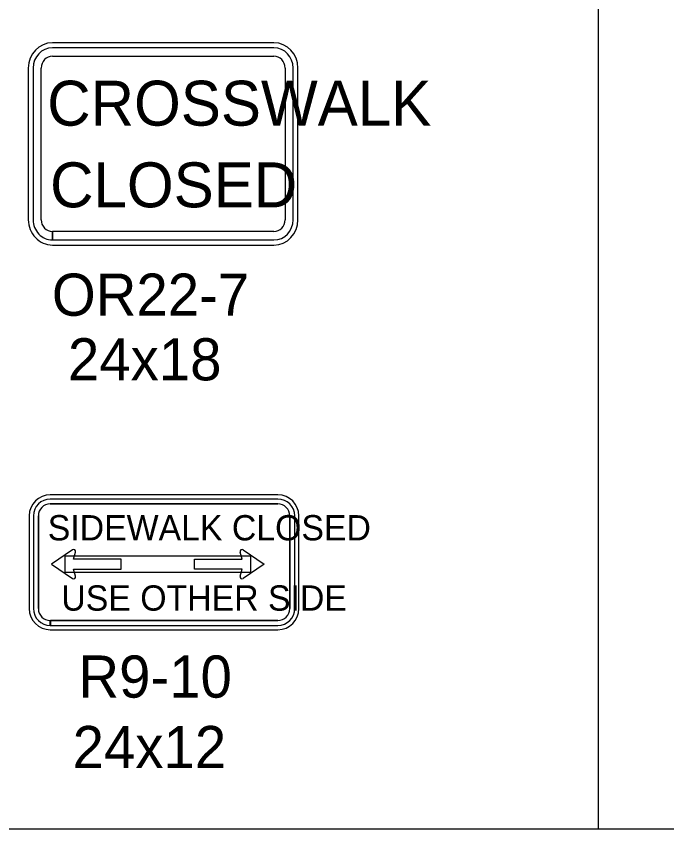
# Model space of a CAD drawing. Extents: x 1458 to 4498, y 17709 to 24109.
# Drawn here: x 2925.6 to 3157.1, y 20667.1 to 20956.1 of the extents above; entities that cross this region are included whole.
import ezdxf

# ---------------------------------------------------------------- set-up
doc = ezdxf.new("R2010")
doc.units = 0
doc.layers.add('P_ODOT_PLAN_TBlock', color=7, linetype='Continuous')
doc.layers.add('P_TRAF_TCP_General', color=7, linetype='Continuous')

msp = doc.modelspace()

# ---------------------------------------------------------------- linework, layer by layer
at = {"layer": 'P_ODOT_PLAN_TBlock'}
for p, q in [((3132.73, 21909.14), (3132.73, 20667.08)), ((1458.44, 20667.08), (3378.44, 20667.08))]:
    msp.add_line(p, q, dxfattribs=at)
at = {"layer": 'P_TRAF_TCP_General'}
for p, q in [((3017.31, 20946.68), (2938.49, 20946.68)), ((3017.31, 20944.88), (2938.49, 20944.88)), ((2938.49, 20941.88), (3017.31, 20941.88)), ((2929.92, 20937.68), (2929.92, 20883.71)), ((2931.63, 20937.68), (2931.63, 20883.71)), ((2934.49, 20883.71), (2934.49, 20937.68)), ((3021.31, 20937.68), (3021.31, 20883.71)), ((3024.17, 20883.71), (3024.17, 20937.68)), ((3025.88, 20883.71), (3025.88, 20937.68)), ((2938.49, 20876.51), (2938.49, 20879.51)), ((3017.31, 20879.51), (2938.51, 20879.51)), ((2938.51, 20879.51), (2938.51, 20876.51)), ((2938.51, 20876.51), (3017.31, 20876.51)), ((2938.49, 20874.71), (3017.31, 20874.71)), ((3018.71, 20785.87), (2937.74, 20785.87)), ((3018.71, 20784.37), (2937.74, 20784.37)), ((3018.71, 20784.37), (2937.74, 20784.37)), ((3018.71, 20782.62), (2937.74, 20782.62)), ((2937.74, 20782.62), (3018.71, 20782.62)), ((2930.24, 20778.37), (2930.24, 20745.39)), ((2931.74, 20778.37), (2931.74, 20745.39)), ((2931.74, 20778.37), (2931.74, 20745.39)), ((2933.49, 20778.37), (2933.49, 20745.39)), ((2933.49, 20745.39), (2933.49, 20778.37)), ((3022.95, 20745.39), (3022.95, 20778.37)), ((3022.95, 20778.37), (3022.95, 20745.39)), ((3024.71, 20745.39), (3024.71, 20778.37)), ((3024.71, 20745.39), (3024.71, 20778.37)), ((3026.21, 20745.39), (3026.21, 20778.37)), ((2945.63, 20766.27), (2938.14, 20761.19)), ((2946.01, 20763), (2946.73, 20765.47)), ((3005.99, 20763), (3005.28, 20765.47)), ((3006.38, 20766.27), (3013.87, 20761.19)), ((2962.91, 20763), (2946.01, 20763)), ((2962.91, 20759.39), (2962.91, 20763)), ((2989.09, 20763), (3005.99, 20763)), ((2989.09, 20759.39), (2989.09, 20763)), ((2938.14, 20761.19), (2945.63, 20756.11)), ((3013.87, 20761.19), (3006.37, 20756.11)), ((2946.72, 20756.94), (2946.01, 20759.39)), ((2946.01, 20759.39), (2962.91, 20759.39)), ((3005.99, 20759.39), (2989.09, 20759.39)), ((3005.28, 20756.94), (3005.99, 20759.39)), ((2937.74, 20741.14), (3018.71, 20741.14)), ((2937.74, 20739.39), (2937.74, 20741.14)), ((3018.71, 20741.14), (2937.76, 20741.14)), ((2937.76, 20741.14), (2937.76, 20739.39)), ((2937.74, 20739.39), (3018.71, 20739.39)), ((2937.74, 20737.89), (3018.71, 20737.89)), ((2937.76, 20739.39), (3018.71, 20739.39))]:
    msp.add_line(p, q, dxfattribs=at)
for points in [[(3009.06, 20764.03), (2942.94, 20764.03), (2942.94, 20758.34), (3009.06, 20758.34)], [(3001.2, 20758.34), (3001.2, 20758.34), (3001.2, 20758.34), (3001.2, 20758.34)]]:
    msp.add_lwpolyline(points, close=True, dxfattribs=at)
for centre, radius, start, end in [((2937.74, 20778.37), 7.5, 90, 180), ((3018.71, 20778.37), 7.5, 0, 90), ((2937.74, 20778.37), 6, 90, 180), ((2937.74, 20778.37), 6, 90, 180), ((3018.71, 20778.37), 6, 0, 90), ((3018.71, 20778.37), 6, 0, 90), ((2937.74, 20778.37), 4.25, 90, 180), ((2937.74, 20778.37), 4.25, 90, 180), ((3018.71, 20778.37), 4.25, 0, 90), ((3018.71, 20778.37), 4.25, 0, 90), ((2946.03, 20765.67), 0.724, 343.8223, 124.116), ((3005.97, 20765.67), 0.724, 55.884, 196.1777), ((2946.03, 20756.72), 0.724, 236.63, 17.4294), ((3005.97, 20756.72), 0.724, 162.5706, 303.37), ((2937.74, 20745.39), 7.5, 180, 270), ((2937.74, 20745.39), 6, 180, 270), ((2937.74, 20745.39), 6, 180, 270), ((2937.74, 20745.39), 4.25, 180, 270), ((2937.74, 20745.39), 4.25, 180, 270), ((3018.71, 20745.39), 6, 270, 0), ((3018.71, 20745.39), 4.25, 270, 0), ((3018.71, 20745.39), 6, 270, 0), ((3018.71, 20745.39), 4.25, 270, 0), ((3018.71, 20745.39), 7.5, 270, 0)]:
    msp.add_arc(centre, radius, start, end, dxfattribs=at)
for centre, major_axis, start_param, end_param in [((2938.49, 20937.68), (0, 9), 0, 1.570796), ((2938.49, 20937.68), (0, 7.2), 0, 1.570796), ((3017.31, 20937.68), (0, 9), 4.712389, 6.283185), ((3017.31, 20937.68), (0, 7.2), 4.712389, 6.283185), ((2938.49, 20937.68), (0, 4.2), 0, 1.570796), ((3017.31, 20937.68), (0, 4.2), 4.712389, 6.283185), ((2938.49, 20883.71), (0, 9), 1.570796, 3.141593), ((2938.49, 20883.71), (0, 7.2), 1.570796, 3.141593), ((2938.49, 20883.71), (0, 4.2), 1.570796, 3.141593), ((3017.31, 20883.71), (0, 7.2), 3.141593, 4.712389), ((3017.31, 20883.71), (0, 4.2), 3.141593, 4.712389), ((3017.31, 20883.71), (0, 9), 3.141593, 4.712389)]:
    msp.add_ellipse(centre, major_axis=major_axis, ratio=0.952417, start_param=start_param, end_param=end_param, dxfattribs=at)

# ---------------------------------------------------------------- texts
for s, height, p in [('CROSSWALK', 15.994, (2936.65, 20917.17)), ('CLOSED', 15.994, (2937.67, 20888.12)), ('OR22-7', 14.994, (2938.31, 20849.56)), ('24x18', 14.994, (2944.03, 20826.57)), ('SIDEWALK CLOSED', 8.9964, (2936.84, 20769.65)), ('USE OTHER SIDE', 8.9964, (2941.68, 20744.66)), ('R9-10', 14.994, (2947.75, 20713.72)), ('24x12', 14.994, (2945.7, 20688.65))]:
    msp.add_text(s, height=height, dxfattribs=at).set_placement(p)

doc.saveas('drawing.dxf')
